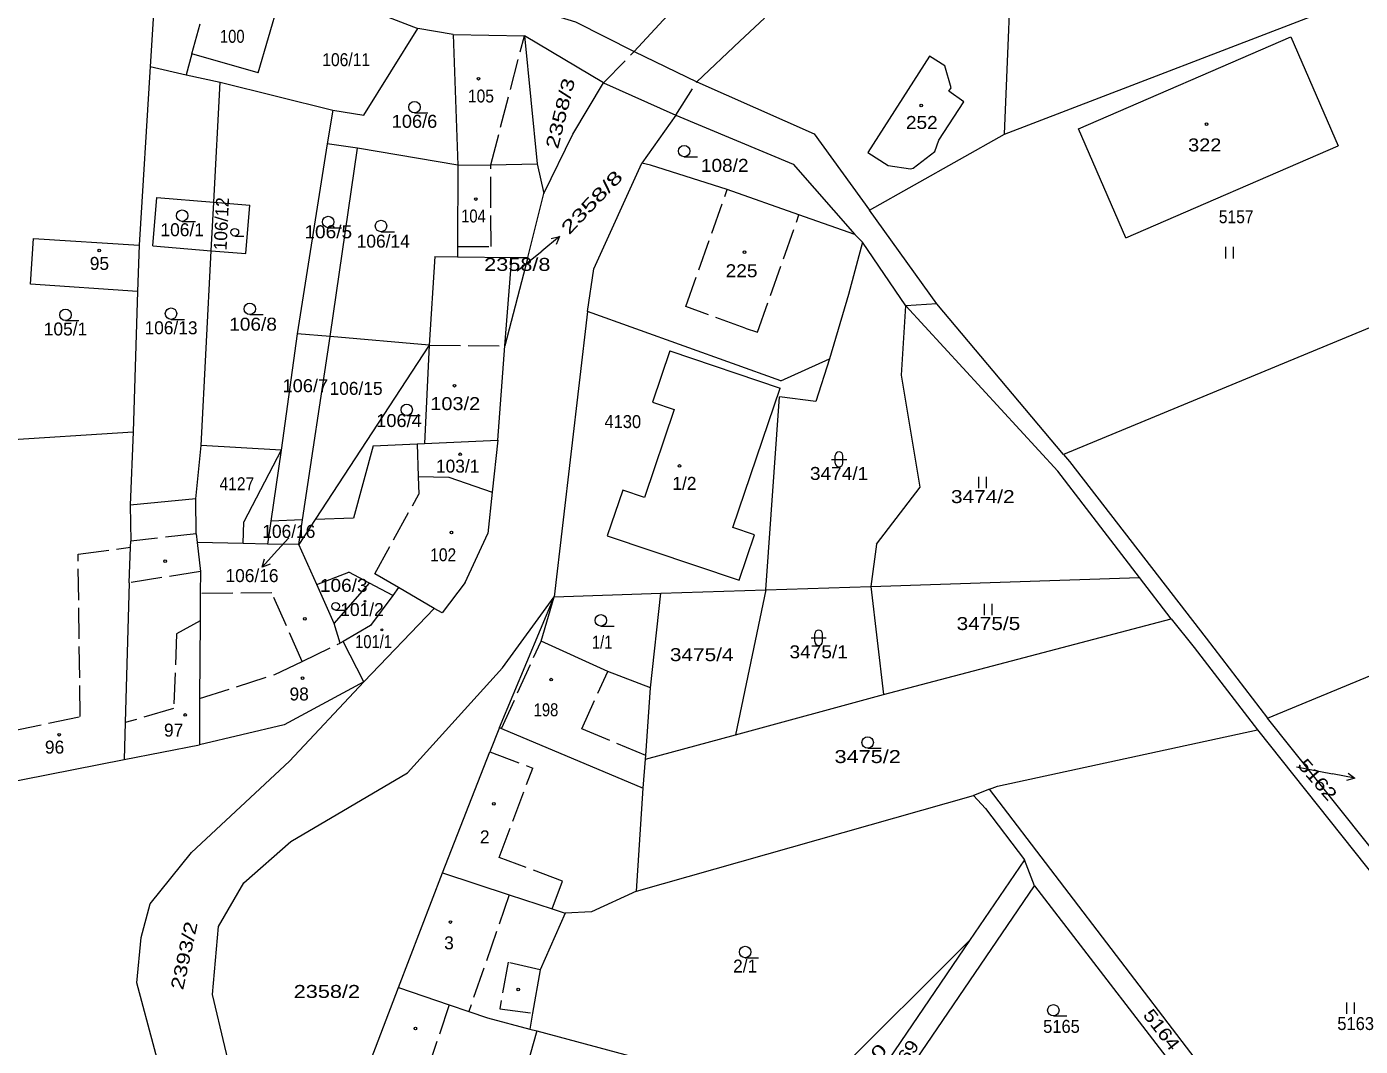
# Model space of a CAD drawing. Extents: x -590528 to -586543, y -1119609 to -1116685.
# Drawn here: x -588705.8 to -588531, y -1118530.4 to -1118396.7 of the extents above; entities that cross this region are included whole.
import ezdxf
from ezdxf.enums import TextEntityAlignment as Align

# ---------------------------------------------------------------- set-up
doc = ezdxf.new("R2010")
doc.units = 0
doc.header["$LTSCALE"] = 0.68
doc.linetypes.add('LONG_DASHED', pattern=[7.5, 6, -1.5])
for name, color, linetype, lineweight in [('1', 7, 'Continuous', 13), ('2', 7, 'LONG_DASHED', 13), ('3', 7, 'Continuous', 13), ('6', 7, 'Continuous', 13)]:
    doc.layers.add(name, color=color, linetype=linetype, lineweight=lineweight)

msp = doc.modelspace()

# ---------------------------------------------------------------- linework, layer by layer
at = {"layer": '1'}
for p, q in [((-588688.67, -1118386.99), (-588689.63, -1118401.93)), ((-588626.19, -1118399.97), (-588615.72, -1118388.66)), ((-588669.43, -1118391.16), (-588654.55, -1118396.94)), ((-588675.46, -1118402.73), (-588672.74, -1118393.49)), ((-588577.61, -1118410.81), (-588531.17, -1118392.89)), ((-588661.6, -1118408.3), (-588654.55, -1118396.94)), ((-588649.9, -1118397.73), (-588654.55, -1118396.94)), ((-588649.9, -1118397.73), (-588649.28, -1118414.88)), ((-588649.9, -1118397.73), (-588640.57, -1118397.9)), ((-588640.57, -1118397.9), (-588638.87, -1118414.68)), ((-588630.21, -1118404.08), (-588640.57, -1118397.9)), ((-588567.91, -1118410.11), (-588540.05, -1118398.02)), ((-588540.05, -1118398.02), (-588533.85, -1118412.32)), ((-588684.17, -1118400.27), (-588684.89, -1118402.99)), ((-588675.46, -1118402.73), (-588684.17, -1118400.27)), ((-588626.19, -1118399.97), (-588617.96, -1118403.95)), ((-588689.63, -1118401.93), (-588691.09, -1118425.36)), ((-588681.28, -1118419.71), (-588680.47, -1118403.98)), ((-588634.2, -1118410.79), (-588630.21, -1118404.08)), ((-588630.21, -1118404.08), (-588620.72, -1118408.31)), ((-588617.96, -1118403.95), (-588602.55, -1118410.73)), ((-588665.7, -1118407.63), (-588661.6, -1118408.3)), ((-588620.72, -1118408.31), (-588625.18, -1118414.58)), ((-588620.72, -1118408.31), (-588605.33, -1118414.73)), ((-588602.55, -1118410.73), (-588595.33, -1118420.76)), ((-588595.33, -1118420.76), (-588577.61, -1118410.81)), ((-588561.72, -1118424.41), (-588567.91, -1118410.11)), ((-588666.43, -1118412.05), (-588670.36, -1118436.97)), ((-588666.03, -1118437.35), (-588662.46, -1118412.65)), ((-588561.72, -1118424.41), (-588533.85, -1118412.32)), ((-588649.28, -1118414.88), (-588649.32, -1118425.55)), ((-588631.46, -1118428.48), (-588625.18, -1118414.58)), ((-588624.02, -1118414.86), (-588625.18, -1118414.58)), ((-588613.97, -1118418.05), (-588624.02, -1118414.86)), ((-588605.33, -1118414.73), (-588597.23, -1118423.97)), ((-588604.56, -1118421.38), (-588613.97, -1118418.05)), ((-588689.26, -1118425.46), (-588688.74, -1118419.1)), ((-588688.74, -1118419.1), (-588681.28, -1118419.71)), ((-588681.28, -1118419.71), (-588676.58, -1118420.1)), ((-588677.1, -1118426.45), (-588676.58, -1118420.1)), ((-588640.11, -1118426.99), (-588638, -1118418.59)), ((-588597.23, -1118423.97), (-588604.56, -1118421.38)), ((-588586.49, -1118433.03), (-588595.33, -1118420.76)), ((-588705.32, -1118430.48), (-588704.91, -1118424.47)), ((-588704.91, -1118424.47), (-588691.09, -1118425.36)), ((-588689.26, -1118425.46), (-588681.61, -1118426.08)), ((-588596.25, -1118424.95), (-588598.08, -1118431.81)), ((-588597.23, -1118423.97), (-588596.25, -1118424.95)), ((-588590.53, -1118433.3), (-588596.25, -1118424.95)), ((-588681.61, -1118426.08), (-588677.1, -1118426.45)), ((-588652.32, -1118426.84), (-588649.35, -1118426.9)), ((-588649.32, -1118425.55), (-588649.35, -1118426.9)), ((-588649.35, -1118426.9), (-588642.21, -1118426.97)), ((-588643.12, -1118438.56), (-588642.21, -1118426.97)), ((-588640.11, -1118426.99), (-588643.12, -1118438.56)), ((-588642.21, -1118426.97), (-588640.11, -1118426.99)), ((-588632.27, -1118434.07), (-588631.46, -1118428.48)), ((-588691.28, -1118431.43), (-588705.32, -1118430.48)), ((-588598.08, -1118431.81), (-588600.57, -1118440.26)), ((-588632.27, -1118434.07), (-588636.65, -1118471.47)), ((-588606.95, -1118443.13), (-588632.27, -1118434.07)), ((-588591.14, -1118442.39), (-588590.53, -1118433.3)), ((-588586.49, -1118433.03), (-588590.53, -1118433.3)), ((-588590.53, -1118433.3), (-588570.63, -1118455.02)), ((-588670.36, -1118436.97), (-588672.47, -1118452.26)), ((-588653.03, -1118438.48), (-588653.67, -1118451.36)), ((-588644.04, -1118450.94), (-588643.12, -1118438.56)), ((-588621.49, -1118439.22), (-588623.76, -1118445.94)), ((-588621.49, -1118439.22), (-588607.04, -1118444.11)), ((-588606.95, -1118443.13), (-588600.57, -1118440.26)), ((-588600.57, -1118440.26), (-588602.36, -1118445.86)), ((-588613.23, -1118462.39), (-588607.04, -1118444.11)), ((-588623.76, -1118445.94), (-588620.92, -1118446.91)), ((-588608.9, -1118470.56), (-588607.13, -1118445.25)), ((-588602.36, -1118445.86), (-588607.13, -1118445.25)), ((-588620.92, -1118446.91), (-588624.83, -1118458.46)), ((-588712.36, -1118451.15), (-588691.84, -1118449.83)), ((-588672.47, -1118452.26), (-588682.92, -1118451.65)), ((-588660.4, -1118451.66), (-588662.96, -1118461.18)), ((-588660.4, -1118451.66), (-588654.6, -1118451.4)), ((-588654.6, -1118451.4), (-588654.48, -1118455.72)), ((-588672.47, -1118452.26), (-588677.35, -1118461.66)), ((-588654.48, -1118455.72), (-588650.47, -1118455.79)), ((-588650.47, -1118455.79), (-588644.77, -1118457.74)), ((-588683.64, -1118458.61), (-588692.24, -1118459.45)), ((-588627.67, -1118457.5), (-588629.69, -1118463.47)), ((-588624.83, -1118458.46), (-588627.67, -1118457.5)), ((-588677.42, -1118464.51), (-588677.35, -1118461.66)), ((-588669.66, -1118461.4), (-588673.8, -1118461.54)), ((-588662.96, -1118461.18), (-588667.99, -1118461.35)), ((-588648.33, -1118469.62), (-588645.36, -1118463.17)), ((-588629.69, -1118463.47), (-588612.41, -1118469.32)), ((-588610.39, -1118463.35), (-588613.23, -1118462.39)), ((-588612.41, -1118469.32), (-588610.39, -1118463.35)), ((-588692.39, -1118469.66), (-588692.21, -1118464.98)), ((-588692.21, -1118464.98), (-588692.18, -1118464.2)), ((-588677.42, -1118464.51), (-588683.46, -1118464.37)), ((-588670.15, -1118464.64), (-588674.23, -1118464.58)), ((-588594.4, -1118464.58), (-588595.16, -1118470.11)), ((-588667.79, -1118469.87), (-588663.6, -1118468.27)), ((-588660.86, -1118469.7), (-588663.6, -1118468.27)), ((-588595.16, -1118470.11), (-588559.91, -1118468.94)), ((-588665.5, -1118475), (-588660.86, -1118469.7)), ((-588657.8, -1118471.29), (-588660.86, -1118469.7)), ((-588657.09, -1118470.26), (-588657.8, -1118471.29)), ((-588648.33, -1118469.62), (-588651.35, -1118473.6)), ((-588608.9, -1118470.56), (-588595.16, -1118470.11)), ((-588595.16, -1118470.11), (-588593.48, -1118484.31)), ((-588643.83, -1118488.63), (-588636.65, -1118471.47)), ((-588643.43, -1118480.8), (-588636.65, -1118471.47)), ((-588638.38, -1118477.31), (-588636.65, -1118471.47)), ((-588636.65, -1118471.47), (-588622.66, -1118471.01)), ((-588624.01, -1118483.44), (-588622.66, -1118471.01)), ((-588652.39, -1118473.01), (-588661.6, -1118482.65)), ((-588593.48, -1118484.31), (-588555.74, -1118474.35)), ((-588555.74, -1118474.35), (-588552.76, -1118478.13)), ((-588661.6, -1118482.65), (-588664.34, -1118477.33)), ((-588552.76, -1118478.13), (-588544.44, -1118488.93)), ((-588655.88, -1118494.58), (-588643.43, -1118480.8)), ((-588661.6, -1118482.65), (-588672.06, -1118488.29)), ((-588671.35, -1118493.05), (-588661.6, -1118482.65)), ((-588612.89, -1118489.59), (-588593.48, -1118484.31)), ((-588672.06, -1118488.29), (-588683.18, -1118490.88)), ((-588492.66, -1118550.88), (-588543.11, -1118487.4)), ((-588643.83, -1118488.63), (-588645.08, -1118491.81)), ((-588643.83, -1118488.63), (-588643.56, -1118488.74)), ((-588643.56, -1118488.74), (-588624.99, -1118496.59)), ((-588624.7, -1118492.79), (-588612.89, -1118489.59)), ((-588578.55, -1118496.3), (-588544.44, -1118488.93)), ((-588544.44, -1118488.93), (-588490.36, -1118556.97)), ((-588693.02, -1118492.81), (-588683.18, -1118490.88)), ((-588651.31, -1118507.67), (-588645.08, -1118491.81)), ((-588714.03, -1118496.94), (-588693.02, -1118492.81)), ((-588625.86, -1118510.11), (-588624.99, -1118496.59)), ((-588579.6, -1118496.72), (-588578.55, -1118496.3)), ((-588625.86, -1118510.11), (-588581.67, -1118497.53)), ((-588580.09, -1118499.23), (-588575, -1118506)), ((-588651.31, -1118507.67), (-588642.54, -1118510.57)), ((-588575, -1118506), (-588582.21, -1118516.58)), ((-588573.68, -1118509.4), (-588575, -1118506)), ((-588593.32, -1118538.22), (-588573.68, -1118509.4)), ((-588642.54, -1118510.57), (-588636.93, -1118512.43)), ((-588625.86, -1118510.11), (-588631.78, -1118512.82)), ((-588636.93, -1118512.43), (-588635.22, -1118513)), ((-588631.78, -1118512.82), (-588635.22, -1118513)), ((-588635.22, -1118513), (-588638.49, -1118520.41)), ((-588602.77, -1118537.06), (-588582.21, -1118516.58)), ((-588582.21, -1118516.58), (-588596.88, -1118538.12)), ((-588657.05, -1118522.74), (-588650.42, -1118524.99)), ((-588645.39, -1118526.69), (-588639.85, -1118528.19)), ((-588638.94, -1118528.43), (-588641.38, -1118537.05)), ((-588639.85, -1118528.19), (-588638.94, -1118528.43)), ((-588638.94, -1118528.43), (-588619.25, -1118533.72))]:
    msp.add_line(p, q, dxfattribs=at)
for points in [[(-588577.61, -1118410.81), (-588576.45, -1118382.23), (-588549.55, -1118371.14)], [(-588637.46, -1118394.95), (-588633.84, -1118396.05), (-588626.19, -1118399.97)], [(-588609.09, -1118395.57), (-588612.31, -1118398.61), (-588617.96, -1118403.95)], [(-588689.63, -1118401.93), (-588684.89, -1118402.99), (-588680.47, -1118403.98)], [(-588680.47, -1118403.98), (-588665.7, -1118407.63), (-588666.43, -1118412.05)], [(-588638.87, -1118414.68), (-588638, -1118418.59), (-588634.2, -1118410.79)], [(-588649.28, -1118414.88), (-588662.46, -1118412.65), (-588666.43, -1118412.05)], [(-588649.28, -1118414.88), (-588644.96, -1118414.8), (-588638.87, -1118414.68)], [(-588682.92, -1118451.65), (-588681.61, -1118426.08), (-588681.28, -1118419.71)], [(-588691.09, -1118425.36), (-588691.28, -1118431.43), (-588691.84, -1118449.83)], [(-588501.37, -1118424.43), (-588569.89, -1118452.8), (-588586.49, -1118433.03)], [(-588543.11, -1118487.4), (-588471.59, -1118457.8), (-588476.86, -1118451.54), (-588481.49, -1118446.13), (-588486.19, -1118440.78), (-588490.97, -1118435.5), (-588495.83, -1118430.28), (-588501.37, -1118424.43)], [(-588652.32, -1118426.84), (-588653.03, -1118438.48), (-588666.03, -1118437.35), (-588670.36, -1118436.97)], [(-588670.15, -1118464.64), (-588669.66, -1118461.4), (-588666.03, -1118437.35)], [(-588653.03, -1118438.48), (-588667.99, -1118461.35), (-588670.15, -1118464.64)], [(-588594.4, -1118464.58), (-588588.69, -1118457.09), (-588591.14, -1118442.39)], [(-588691.84, -1118449.83), (-588692.24, -1118459.45), (-588692.18, -1118464.2)], [(-588683.58, -1118463.2), (-588683.64, -1118458.61), (-588682.92, -1118451.65)], [(-588654.6, -1118451.4), (-588653.67, -1118451.36), (-588644.04, -1118450.94)], [(-588644.04, -1118450.94), (-588644.77, -1118457.74), (-588645.36, -1118463.17)], [(-588672.47, -1118452.26), (-588673.8, -1118461.54), (-588674.23, -1118464.58)], [(-588569.89, -1118452.8), (-588569.1, -1118453.73), (-588551.18, -1118476.91), (-588543.11, -1118487.4)], [(-588555.74, -1118474.35), (-588559.91, -1118468.94), (-588570.63, -1118455.02)], [(-588683.58, -1118463.2), (-588683.46, -1118464.37), (-588683.05, -1118468.16)], [(-588665.5, -1118475), (-588667.79, -1118469.87), (-588670.15, -1118464.64)], [(-588683.05, -1118468.16), (-588683.07, -1118471.04), (-588683.09, -1118474.65), (-588683.15, -1118484.82), (-588683.18, -1118490.88)], [(-588692.39, -1118469.66), (-588692.89, -1118487.99), (-588693.02, -1118492.81)], [(-588651.35, -1118473.6), (-588652.39, -1118473.01), (-588657.09, -1118470.26)], [(-588622.66, -1118471.01), (-588608.9, -1118470.56), (-588612.89, -1118489.59)], [(-588657.8, -1118471.29), (-588660.76, -1118475.24), (-588664.34, -1118477.33), (-588664.73, -1118477.55), (-588665.5, -1118475)], [(-588624.66, -1118492.3), (-588624.01, -1118483.44), (-588629.63, -1118481.27), (-588638.38, -1118477.31)], [(-588689.62, -1118511.77), (-588684.22, -1118505.04), (-588671.35, -1118493.05)], [(-588624.99, -1118496.59), (-588624.7, -1118492.79), (-588624.66, -1118492.3)], [(-588680.66, -1118514.72), (-588677.36, -1118508.99), (-588671.19, -1118503.58), (-588655.88, -1118494.58)], [(-588579.6, -1118496.72), (-588581.67, -1118497.53), (-588580.09, -1118499.23)], [(-588525.61, -1118564.4), (-588527.9, -1118564.4), (-588579.6, -1118496.72)], [(-588661.33, -1118533.96), (-588657.05, -1118522.74), (-588651.31, -1118507.67)], [(-588573.68, -1118509.4), (-588551.33, -1118538.42), (-588540.68, -1118552.23), (-588602.69, -1118551.95)], [(-588682.13, -1118556.73), (-588691.38, -1118522.13), (-588690.83, -1118516.18), (-588689.62, -1118511.77)], [(-588673.36, -1118557.76), (-588681.44, -1118523.65), (-588680.66, -1118514.72)], [(-588638.49, -1118520.41), (-588639.48, -1118526.1), (-588639.85, -1118528.19)], [(-588650.42, -1118524.99), (-588647.85, -1118525.86), (-588645.39, -1118526.69)]]:
    msp.add_lwpolyline(points, dxfattribs=at)
msp.add_lwpolyline([(-588584.61, -1118404.7), (-588585.42, -1118401.84), (-588587.44, -1118400.55), (-588595.52, -1118413.21), (-588592.88, -1118414.91), (-588589.93, -1118415.34), (-588589.59, -1118415.25), (-588586.75, -1118413.07), (-588586.22, -1118411.59), (-588582.93, -1118406.56), (-588584.93, -1118405.15)], close=True, dxfattribs=at)
at = {"layer": '2'}
for p, q in [((-588684.17, -1118400.27), (-588680.86, -1118388.53)), ((-588644.96, -1118414.8), (-588640.57, -1118397.9)), ((-588630.21, -1118404.08), (-588626.19, -1118399.97)), ((-588620.72, -1118408.31), (-588617.96, -1118403.95)), ((-588644.94, -1118425.55), (-588644.96, -1118414.8)), ((-588619.38, -1118433.41), (-588613.97, -1118418.05)), ((-588610.01, -1118436.76), (-588604.56, -1118421.38)), ((-588649.32, -1118425.55), (-588644.94, -1118425.55)), ((-588611.63, -1118436.23), (-588619.38, -1118433.41)), ((-588611.63, -1118436.23), (-588610.01, -1118436.76)), ((-588653.03, -1118438.48), (-588643.12, -1118438.56)), ((-588654.48, -1118455.72), (-588654.41, -1118458.03)), ((-588660.19, -1118468.45), (-588654.41, -1118458.03)), ((-588683.58, -1118463.2), (-588692.18, -1118464.2)), ((-588699.08, -1118465.91), (-588692.21, -1118464.98)), ((-588674.23, -1118464.58), (-588677.42, -1118464.51)), ((-588683.05, -1118468.16), (-588692.39, -1118469.66)), ((-588657.09, -1118470.26), (-588660.19, -1118468.45)), ((-588673.68, -1118470.98), (-588683.07, -1118471.04)), ((-588669.71, -1118479.95), (-588673.68, -1118470.98)), ((-588683.09, -1118474.65), (-588686.16, -1118476.34)), ((-588686.16, -1118476.34), (-588686.55, -1118486.12)), ((-588643.56, -1118488.74), (-588638.38, -1118477.31)), ((-588633.04, -1118488.78), (-588629.63, -1118481.27)), ((-588683.15, -1118484.82), (-588673.3, -1118481.68)), ((-588686.55, -1118486.12), (-588692.89, -1118487.99)), ((-588624.66, -1118492.3), (-588633.04, -1118488.78)), ((-588645.08, -1118491.81), (-588639.46, -1118493.96)), ((-588643.85, -1118505.67), (-588639.46, -1118493.96)), ((-588635.56, -1118508.78), (-588643.85, -1118505.67)), ((-588636.93, -1118512.43), (-588635.56, -1118508.78)), ((-588642.54, -1118510.57), (-588647.85, -1118525.86)), ((-588642.7, -1118519.43), (-588643.8, -1118525.51)), ((-588638.49, -1118520.41), (-588642.7, -1118519.43)), ((-588650.42, -1118524.99), (-588653.17, -1118533.24)), ((-588643.8, -1118525.51), (-588639.48, -1118526.1))]:
    msp.add_line(p, q, dxfattribs=at)
for points in [[(-588707.93, -1118489.12), (-588698.8, -1118487.2), (-588699.08, -1118465.91)], [(-588673.3, -1118481.68), (-588669.71, -1118479.95), (-588664.73, -1118477.55)]]:
    msp.add_lwpolyline(points, dxfattribs=at)
at = {"layer": '3'}
for p, q in [((-588635.94, -1118424.24), (-588638.27, -1118426.13)), ((-588641.49, -1118428.73), (-588638.27, -1118426.13)), ((-588671.45, -1118463.75), (-588672.92, -1118465.37)), ((-588674.935, -1118467.592), (-588672.92, -1118465.37)), ((-588539.32, -1118493.8), (-588534.63, -1118494.71)), ((-588531.684, -1118495.278), (-588534.63, -1118494.71))]:
    msp.add_line(p, q, dxfattribs=at)
for points in [[(-588637.031, -1118424.482), (-588635.94, -1118424.24), (-588636.402, -1118425.259)], [(-588673.894, -1118467.187), (-588674.935, -1118467.592), (-588674.634, -1118466.515)], [(-588532.571, -1118494.599), (-588531.684, -1118495.278), (-588532.761, -1118495.58)]]:
    msp.add_lwpolyline(points, dxfattribs=at)
at = {"layer": '6'}
for p, q in [((-588654.97, -1118408.01), (-588653.22, -1118408.01)), ((-588619.62, -1118413.76), (-588617.87, -1118413.76)), ((-588685.43, -1118422.23), (-588683.68, -1118422.23)), ((-588666.28, -1118423.06), (-588664.53, -1118423.06)), ((-588659.36, -1118423.59), (-588657.61, -1118423.59)), ((-588678.53, -1118424.162), (-588677.358, -1118424.162)), ((-588548.61, -1118427.09), (-588548.61, -1118425.59)), ((-588547.61, -1118427.09), (-588547.61, -1118425.59)), ((-588700.73, -1118435.25), (-588698.98, -1118435.25)), ((-588686.89, -1118435.09), (-588685.14, -1118435.09)), ((-588676.57, -1118434.47), (-588674.82, -1118434.47)), ((-588655.99, -1118447.7), (-588654.24, -1118447.7)), ((-588600.3, -1118453.45), (-588598.3, -1118453.45)), ((-588599.8, -1118453.95), (-588599.8, -1118452.95)), ((-588598.8, -1118453.95), (-588598.8, -1118452.95)), ((-588580.96, -1118457.24), (-588580.96, -1118455.74)), ((-588579.96, -1118457.24), (-588579.96, -1118455.74)), ((-588580.22, -1118473.89), (-588580.22, -1118472.39)), ((-588579.22, -1118473.89), (-588579.22, -1118472.39)), ((-588665.32, -1118473.222), (-588664.148, -1118473.222)), ((-588630.54, -1118475.32), (-588628.79, -1118475.32)), ((-588602.98, -1118476.85), (-588600.98, -1118476.85)), ((-588602.48, -1118477.35), (-588602.48, -1118476.35)), ((-588601.48, -1118477.35), (-588601.48, -1118476.35)), ((-588595.55, -1118491.34), (-588593.8, -1118491.34)), ((-588611.62, -1118518.82), (-588609.87, -1118518.82)), ((-588532.73, -1118526.18), (-588532.73, -1118524.68)), ((-588531.73, -1118526.18), (-588531.73, -1118524.68)), ((-588571.21, -1118526.47), (-588569.46, -1118526.47))]:
    msp.add_line(p, q, dxfattribs=at)
for centre, radius in [((-588646.5802, -1118403.5204), 0.175), ((-588654.97, -1118407.26), 0.75), ((-588588.5202, -1118407.0404), 0.175), ((-588551.1102, -1118409.4904), 0.175), ((-588619.62, -1118413.01), 0.75), ((-588646.9302, -1118419.3004), 0.175), ((-588685.43, -1118421.48), 0.75), ((-588666.28, -1118422.31), 0.75), ((-588678.53, -1118423.66), 0.5025), ((-588659.36, -1118422.84), 0.75), ((-588696.3002, -1118426.0504), 0.175), ((-588611.6902, -1118426.2604), 0.175), ((-588700.73, -1118434.5), 0.75), ((-588686.89, -1118434.34), 0.75), ((-588676.57, -1118433.72), 0.75), ((-588649.7202, -1118443.7904), 0.175), ((-588655.99, -1118446.95), 0.75), ((-588648.9902, -1118452.7904), 0.175), ((-588620.2302, -1118454.3204), 0.175), ((-588650.1402, -1118463.0404), 0.175), ((-588687.6702, -1118466.8204), 0.175), ((-588665.32, -1118472.72), 0.5025), ((-588661.4601, -1118472.0702), 0.1172), ((-588669.3402, -1118474.3604), 0.175), ((-588630.54, -1118474.57), 0.75), ((-588659.2401, -1118475.8202), 0.1172), ((-588669.6402, -1118482.1504), 0.175), ((-588637.0402, -1118482.3504), 0.175), ((-588685.0302, -1118486.9804), 0.175), ((-588701.5702, -1118489.5704), 0.175), ((-588595.55, -1118490.59), 0.75), ((-588644.5602, -1118498.6504), 0.175), ((-588650.2702, -1118514.1404), 0.175), ((-588611.62, -1118518.07), 0.75), ((-588641.3602, -1118522.9804), 0.175), ((-588571.21, -1118525.72), 0.75), ((-588654.8602, -1118528.1004), 0.175)]:
    msp.add_circle(centre, radius, dxfattribs=at)
for centre, start, end in [((-588599.3, -1118452.95), 0, 179.99999), ((-588599.3, -1118453.95), 179.99999, 359.99999), ((-588601.98, -1118476.35), 0, 179.99999), ((-588601.98, -1118477.35), 179.99999, 359.99999)]:
    msp.add_arc(centre, 0.5, start, end, dxfattribs=at)

# ---------------------------------------------------------------- texts
at = {"layer": '3'}
for s, width, p in [('100', 0.85, (-588678.8605, -1118398.81)), ('106/11', 0.9, (-588663.93, -1118401.87)), ('105', 0.9, (-588646.2605, -1118406.64)), ('106/6', 1.05, (-588654.9705, -1118409.96)), ('322', 1.15, (-588551.361, -1118413.06)), ('108/2', 1.1, (-588614.3, -1118415.74)), ('104', 0.85, (-588647.2405, -1118422.38)), ('106/5', 1.1, (-588666.2795, -1118424.45)), ('2358/8', 1.25, (-588641.49, -1118428.73)), ('225', 1.1, (-588612.09, -1118429.56)), ('106/8', 1.1, (-588676.14, -1118436.57)), ('106/7', 1.05, (-588669.2805, -1118444.64)), ('103/2', 1.15, (-588649.6305, -1118446.99)), ('106/4', 1.05, (-588657.0015, -1118449.21)), ('4130', 0.95, (-588627.66, -1118449.35)), ('3474/1', 1.1, (-588599.3, -1118456.15)), ('4127', 0.9, (-588678.2605, -1118457.5)), ('3474/2', 1.2, (-588580.4605, -1118459.19)), ('102', 0.9, (-588651.2105, -1118466.82)), ('106/3', 1.1, (-588664.2495, -1118470.83)), ('3475/5', 1.2, (-588579.72, -1118475.84)), ('101/1', 0.85, (-588660.3405, -1118478.21)), ('1/1', 0.85, (-588630.371, -1118478.28)), ('3475/1', 1.1, (-588601.98, -1118479.55)), ('3475/4', 1.2, (-588617.31, -1118479.92)), ('198', 0.85, (-588637.73, -1118487.15)), ('3475/2', 1.25, (-588595.5505, -1118493.29)), ('2358/2', 1.25, (-588666.46, -1118524.1))]:
    msp.add_text(s, height=1.7, dxfattribs=dict(at, width=width)).set_placement(p, align=Align.CENTER)
for s, rotation, width, p in [('2358/3', 75.974, 1.35, (-588635.0285, -1118408.2635)), ('2393/2', 77.693, 1.3, (-588684.3503, -1118518.7192)), ('990', 48.014, 1.45, (-588594.7083, -1118533.0911))]:
    msp.add_text(s, height=1.7, rotation=rotation, dxfattribs=dict(at, width=width)).set_placement(p, align=Align.CENTER)
for s, width, p in [('252', 1.1, (-588590.543, -1118410.11)), ('5157', 0.9, (-588549.513, -1118422.47)), ('5165', 0.95, (-588572.543, -1118528.68)), ('5163', 0.95, (-588533.973, -1118528.31))]:
    msp.add_text(s, height=1.7, dxfattribs=dict(at, width=width)).set_placement(p)
for s, rotation, width, p in [('2358/8', 46.41, 1.5, (-588634.706, -1118424.088)), ('5162', 310.83, 1.25, (-588539.294, -1118493.628)), ('5164', 307.736, 1.2, (-588559.545, -1118526.378)), ('5169', 55.749, 1.15, (-588591.986, -1118535.174))]:
    msp.add_text(s, height=1.7, rotation=rotation, dxfattribs=dict(at, width=width)).set_placement(p)
msp.add_text('106/12', height=1.7, rotation=87.261, dxfattribs=at).set_placement((-588679.4476, -1118422.5986), align=Align.CENTER)
for s, p in [('106/1', (-588685.4305, -1118424.18)), ('106/14', (-588659.07, -1118425.68)), ('95', (-588696.2805, -1118428.6)), ('105/1', (-588700.7305, -1118437.2)), ('106/13', (-588686.89, -1118437.04)), ('106/15', (-588662.6305, -1118444.99)), ('103/1', (-588649.3105, -1118455.19)), ('1/2', (-588619.58, -1118457.45)), ('106/16', (-588671.45, -1118463.75)), ('101/2', (-588661.851, -1118474)), ('98', (-588670.09, -1118485.08)), ('97', (-588686.5505, -1118489.82)), ('96', (-588702.1605, -1118492.05)), ('2', (-588645.76, -1118503.82)), ('3', (-588650.4505, -1118517.72)), ('2/1', (-588611.62, -1118520.77))]:
    msp.add_text(s, height=1.7, dxfattribs=at).set_placement(p, align=Align.CENTER)
msp.add_text('106/16', height=1.7, dxfattribs=at).set_placement((-588672.798, -1118469.55), align=Align.RIGHT)

doc.saveas('drawing.dxf')
